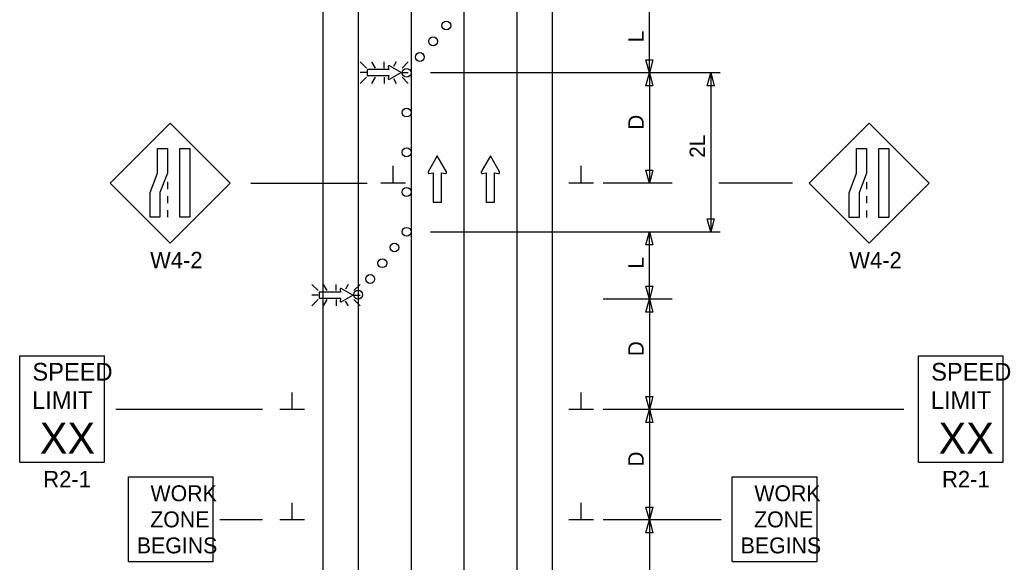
# Model space of a CAD drawing. Extents: x 16489 to 18480, y 5759 to 7026.
# Drawn here: x 16734.3 to 17180.5, y 6441.9 to 6687.7 of the extents above; entities that cross this region are included whole.
import ezdxf

# ---------------------------------------------------------------- set-up
doc = ezdxf.new("R2010")
doc.units = 0
for name, color, linetype in [('ALI_LEGAL_EX', 7, 'Continuous'), ('MT_SCRATCH_LEVEL_E', 7, 'Continuous'), ('PAVT_EDGE_EX', 7, 'Continuous'), ('TRAFFIC_SIGNS_PR', 7, 'Continuous'), ('TYPICAL_TEXT_DIMEN_PR', 7, 'Continuous')]:
    doc.layers.add(name, color=color, linetype=linetype)

msp = doc.modelspace()

# ---------------------------------------------------------------- linework, layer by layer
at = {"layer": 'ALI_LEGAL_EX'}
for p, q in [((16911.66, 7026.35), (16911.66, 6197.16)), ((16935.66, 7026.35), (16935.66, 6197.16)), ((16935.66, 7026.35), (16935.66, 6197.16))]:
    msp.add_line(p, q, dxfattribs=at)
for points in [[(16911.66, 6626.35), (16911.66, 6601.35)], [(16935.66, 6626.35), (16935.66, 6601.35)], [(16911.66, 6526.35), (16911.66, 6501.35)], [(16935.66, 6526.35), (16935.66, 6501.35)]]:
    msp.add_lwpolyline(points, dxfattribs=at)
at = {"layer": 'MT_SCRATCH_LEVEL_E'}
for p, q in [((16923.57, 6625.97), (16919.46, 6618.73)), ((16927.71, 6618.73), (16923.57, 6625.97)), ((16947.62, 6625.97), (16943.51, 6618.73)), ((16951.77, 6618.73), (16947.62, 6625.97)), ((16919.94, 6618.04), (16921.72, 6618.36)), ((16921.72, 6618.36), (16921.72, 6605.1)), ((16925.46, 6605.1), (16925.46, 6618.36)), ((16925.46, 6618.36), (16927.23, 6618.04)), ((16943.99, 6618.04), (16945.77, 6618.36)), ((16945.77, 6618.36), (16945.77, 6605.1)), ((16949.51, 6605.1), (16949.51, 6618.36)), ((16949.51, 6618.36), (16951.29, 6618.04)), ((16921.72, 6605.1), (16925.46, 6605.1)), ((16945.77, 6605.1), (16949.51, 6605.1))]:
    msp.add_line(p, q, dxfattribs=at)
for centre, start, end in [((16919.86, 6618.5), 150.4248, 279.9638), ((16927.3, 6618.5), 260.0362, 29.7731), ((16943.92, 6618.5), 150.4248, 279.9638), ((16951.36, 6618.5), 260.0362, 29.7731)]:
    msp.add_arc(centre, 0.463, start, end, dxfattribs=at)
at = {"layer": 'PAVT_EDGE_EX'}
for p, q in [((16871.66, 6926.66), (16871.66, 6108.7)), ((16887.66, 6926.66), (16887.66, 6108.7)), ((16959.66, 6926.66), (16959.66, 6108.7)), ((16975.66, 6926.66), (16975.66, 6108.7))]:
    msp.add_line(p, q, dxfattribs=at)
at = {"layer": 'TRAFFIC_SIGNS_PR'}
for p, q in [((16891.44, 6665.74), (16888.62, 6668.56)), ((16893.74, 6668.56), (16895.36, 6665.74)), ((16899.52, 6665.74), (16899.52, 6668.56)), ((16904.99, 6668.56), (16903.79, 6666.46)), ((16910.43, 6668.55), (16907.61, 6665.74)), ((16891.44, 6663.7), (16888.62, 6663.7)), ((16891.44, 6661.67), (16888.62, 6658.85)), ((16895.39, 6661.67), (16893.76, 6658.85)), ((16899.52, 6661.67), (16899.52, 6658.85)), ((16903.71, 6661.04), (16904.97, 6658.85)), ((16907.61, 6663.7), (16910.43, 6663.7)), ((16910.43, 6658.85), (16907.61, 6661.67)), ((16802.49, 6640.84), (16775.34, 6613.69)), ((16829.64, 6613.69), (16802.49, 6640.84)), ((17119.29, 6640.79), (17092.13, 6613.64)), ((17146.44, 6613.64), (17119.29, 6640.79)), ((16775.34, 6613.69), (16802.49, 6586.53)), ((16801.24, 6614.18), (16801.24, 6610.98)), ((16802.49, 6586.53), (16829.64, 6613.69)), ((17092.13, 6613.64), (17119.29, 6586.49)), ((17118.04, 6614.13), (17118.04, 6610.93)), ((17119.29, 6586.49), (17146.44, 6613.64)), ((16801.24, 6607.78), (16801.24, 6604.58)), ((17118.04, 6607.73), (17118.04, 6604.53)), ((16801.24, 6601.38), (16801.24, 6598.18)), ((17118.04, 6601.33), (17118.04, 6598.13)), ((16869.6, 6564.95), (16866.78, 6567.77)), ((16871.9, 6567.77), (16873.52, 6564.95)), ((16877.68, 6564.95), (16877.68, 6567.77)), ((16883.15, 6567.77), (16881.94, 6565.68)), ((16888.59, 6567.77), (16885.77, 6564.95)), ((16869.6, 6562.92), (16866.78, 6562.92)), ((16885.77, 6562.92), (16888.59, 6562.92)), ((16869.6, 6560.88), (16866.78, 6558.06)), ((16873.55, 6560.88), (16871.92, 6558.06)), ((16877.68, 6560.88), (16877.68, 6558.06)), ((16881.87, 6560.25), (16883.13, 6558.06)), ((16888.59, 6558.07), (16885.77, 6560.88)), ((16734.34, 6535.36), (16772.79, 6535.36)), ((16734.34, 6487.3), (16734.34, 6535.36)), ((16772.79, 6487.3), (16772.79, 6535.36)), ((17141.58, 6535.36), (17180.03, 6535.36)), ((17141.58, 6487.3), (17141.58, 6535.36)), ((17180.03, 6487.3), (17180.03, 6535.36)), ((16734.34, 6487.3), (16772.79, 6487.3)), ((17141.58, 6487.3), (17180.03, 6487.3)), ((16783.62, 6442.19), (16783.62, 6480.59)), ((16783.62, 6480.59), (16822.02, 6480.59)), ((16822.02, 6442.19), (16822.02, 6480.59)), ((17057.23, 6442.19), (17057.23, 6480.59)), ((17057.23, 6480.59), (17095.63, 6480.59)), ((17095.63, 6442.19), (17095.63, 6480.59)), ((16783.62, 6442.19), (16822.02, 6442.19)), ((17057.23, 6442.19), (17095.63, 6442.19))]:
    msp.add_line(p, q, dxfattribs=at)
for points in [[(16901.35, 6666.39), (16901.58, 6665.09), (16891.86, 6665.09), (16891.86, 6662.35), (16901.58, 6662.35), (16901.35, 6661.04)], [(16901.85, 6660.69), (16907.16, 6663.7), (16901.85, 6666.74)], [(16879.51, 6565.6), (16879.74, 6564.3), (16870.02, 6564.3), (16870.02, 6561.56), (16879.74, 6561.56), (16879.51, 6560.26)], [(16880.01, 6559.9), (16885.32, 6562.92), (16880.01, 6565.96)]]:
    msp.add_lwpolyline(points, dxfattribs=at)
for points in [[(16801.24, 6629.42), (16801.24, 6618.24), (16797.9, 6609.36), (16797.9, 6598.18), (16793.4, 6598.18), (16793.4, 6609.36), (16796.75, 6618.24), (16796.75, 6629.42)], [(16811.38, 6629.42), (16811.38, 6598.18), (16806.88, 6598.18), (16806.88, 6629.42)], [(17118.04, 6629.38), (17118.04, 6618.19), (17114.69, 6609.31), (17114.69, 6598.13), (17110.2, 6598.13), (17110.2, 6609.31), (17113.54, 6618.19), (17113.54, 6629.38)], [(17128.17, 6629.38), (17128.17, 6598.13), (17123.68, 6598.13), (17123.68, 6629.38)]]:
    msp.add_lwpolyline(points, close=True, dxfattribs=at)
for centre in [(16927.66, 6685.05), (16921.66, 6677.91), (16915.66, 6670.77), (16909.66, 6663.63), (16909.66, 6645.63), (16909.66, 6627.63), (16909.66, 6609.63), (16909.66, 6591.63), (16904.17, 6584.5), (16898.67, 6577.37), (16893.17, 6570.24), (16887.67, 6563.12)]:
    msp.add_circle(centre, 2, dxfattribs=at)
for centre, start, end in [((16901.69, 6666.44), 61.4833, 189.9593), ((16901.69, 6660.99), 170.7308, 298.8916), ((16879.85, 6565.66), 61.4833, 189.9593), ((16879.85, 6560.2), 170.7308, 298.8916)]:
    msp.add_arc(centre, 0.341, start, end, dxfattribs=at)
at = {"layer": 'TYPICAL_TEXT_DIMEN_PR'}
for p, q in [((17019.66, 6663.63), (17019.66, 6694.2)), ((17019.66, 6663.63), (17018.09, 6669.49)), ((17018.09, 6669.49), (17019.66, 6669.49)), ((17019.66, 6669.49), (17021.23, 6669.49)), ((17021.23, 6669.49), (17019.66, 6663.63)), ((17051.71, 6663.63), (16920.56, 6663.63)), ((17018.09, 6657.77), (17019.66, 6663.63)), ((17019.66, 6663.63), (17019.66, 6613.63)), ((17019.66, 6663.63), (17021.23, 6657.77)), ((17045.9, 6657.77), (17047.47, 6663.63)), ((17047.47, 6663.63), (17049.04, 6657.77)), ((17047.47, 6663.63), (17047.47, 6591.63)), ((17019.66, 6657.77), (17018.09, 6657.77)), ((17021.23, 6657.77), (17019.66, 6657.77)), ((17047.47, 6657.77), (17045.9, 6657.77)), ((17049.04, 6657.77), (17047.47, 6657.77)), ((16903.59, 6613.63), (16903.59, 6621.42)), ((16988.79, 6613.63), (16988.79, 6621.42)), ((17019.66, 6613.63), (17018.09, 6619.49)), ((17018.09, 6619.49), (17019.66, 6619.49)), ((17019.66, 6619.49), (17021.23, 6619.49)), ((17021.23, 6619.49), (17019.66, 6613.63)), ((17047.47, 6618.5), (17047.47, 6614.73)), ((16839.11, 6613.63), (16891.86, 6613.63)), ((16909.22, 6613.63), (16897.97, 6613.63)), ((16994.41, 6613.63), (16983.16, 6613.63)), ((17029.93, 6613.63), (16998.66, 6613.63)), ((17084.44, 6613.63), (17051.1, 6613.63)), ((17047.47, 6591.63), (17045.9, 6597.49)), ((17045.9, 6597.49), (17047.47, 6597.49)), ((17047.47, 6597.49), (17049.04, 6597.49)), ((17049.04, 6597.49), (17047.47, 6591.63)), ((16920.56, 6591.63), (17051.71, 6591.63)), ((17018.09, 6585.77), (17019.66, 6591.63)), ((17019.66, 6561.07), (17019.66, 6591.63)), ((17019.66, 6591.63), (17021.23, 6585.77)), ((17019.66, 6585.77), (17018.09, 6585.77)), ((17021.23, 6585.77), (17019.66, 6585.77)), ((17019.66, 6561.07), (17018.09, 6566.93)), ((17018.09, 6566.93), (17019.66, 6566.93)), ((17019.66, 6566.93), (17021.23, 6566.93)), ((17021.23, 6566.93), (17019.66, 6561.07)), ((17029.93, 6561.07), (16998.66, 6561.07)), ((17018.09, 6555.21), (17019.66, 6561.07)), ((17019.66, 6561.07), (17019.66, 6511.07)), ((17019.66, 6561.07), (17021.23, 6555.21)), ((17019.66, 6555.21), (17018.09, 6555.21)), ((17021.23, 6555.21), (17019.66, 6555.21)), ((16857.78, 6511.07), (16857.78, 6518.85)), ((16988.79, 6511.07), (16988.79, 6518.85)), ((17019.66, 6511.07), (17018.09, 6516.93)), ((17018.09, 6516.93), (17019.66, 6516.93)), ((17019.66, 6516.93), (17021.23, 6516.93)), ((17021.23, 6516.93), (17019.66, 6511.07)), ((16844.35, 6511.07), (16777.89, 6511.07)), ((16863.4, 6511.07), (16852.15, 6511.07)), ((16994.41, 6511.07), (16983.16, 6511.07)), ((17026.51, 6511.07), (16998.66, 6511.07)), ((17018.09, 6505.21), (17019.66, 6511.07)), ((17019.66, 6511.07), (17019.66, 6461.07)), ((17019.66, 6511.07), (17021.23, 6505.21)), ((17134.98, 6511.07), (17026.51, 6511.07)), ((17019.66, 6505.21), (17018.09, 6505.21)), ((17021.23, 6505.21), (17019.66, 6505.21)), ((16857.78, 6461.07), (16857.78, 6468.85)), ((16988.79, 6461.07), (16988.79, 6468.85)), ((17019.66, 6461.07), (17018.09, 6466.93)), ((17018.09, 6466.93), (17019.66, 6466.93)), ((17019.66, 6466.93), (17021.23, 6466.93)), ((17021.23, 6466.93), (17019.66, 6461.07)), ((16844.35, 6461.07), (16825.01, 6461.07)), ((16863.4, 6461.07), (16852.15, 6461.07)), ((16994.41, 6461.07), (16983.16, 6461.07)), ((17026.51, 6461.07), (16998.66, 6461.07)), ((17018.09, 6455.21), (17019.66, 6461.07)), ((17019.66, 6461.07), (17019.66, 6411.07)), ((17019.66, 6461.07), (17021.23, 6455.21)), ((17052.19, 6461.07), (17026.51, 6461.07)), ((17019.66, 6455.21), (17018.09, 6455.21)), ((17021.23, 6455.21), (17019.66, 6455.21))]:
    msp.add_line(p, q, dxfattribs=at)

# ---------------------------------------------------------------- texts
at = {"layer": 'TRAFFIC_SIGNS_PR'}
for s, height, p in [('W4-2', 7.44, (16793.45, 6575.09)), ('W4-2', 7.44, (17110.24, 6575.05)), ('SPEED', 8.01, (16740.11, 6524.21)), ('SPEED', 8.01, (17147.36, 6524.21)), ('LIMIT', 8.01, (16739.95, 6511.4)), ('LIMIT', 8.01, (17147.2, 6511.4)), ('XX', 14.048, (16743.46, 6491.07)), ('XX', 14.048, (17150.71, 6491.07)), ('R2-1', 7.449, (16745.03, 6475.85)), ('R2-1', 7.449, (17152.27, 6475.85)), ('WORK', 7.217, (16793.62, 6469.55)), ('WORK', 7.217, (17067.23, 6469.55)), ('ZONE', 7.217, (16793.5, 6457.74)), ('ZONE', 7.217, (17067.11, 6457.74)), ('BEGINS', 7.217, (16787.43, 6445.94)), ('BEGINS', 7.217, (17061.04, 6445.94))]:
    msp.add_text(s, height=height, dxfattribs=at).set_placement(p)
at = {"layer": 'TYPICAL_TEXT_DIMEN_PR'}
for s, p in [('L', (17017.1, 6677.49)), ('D', (17017.1, 6637.85)), ('2L', (17044.91, 6625.14)), ('L', (17017.1, 6574.93)), ('D', (17017.11, 6535.29)), ('D', (17017.11, 6485.29))]:
    msp.add_text(s, height=7, rotation=90, dxfattribs=at).set_placement(p)

doc.saveas('drawing.dxf')
